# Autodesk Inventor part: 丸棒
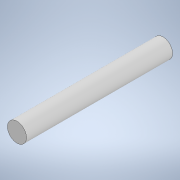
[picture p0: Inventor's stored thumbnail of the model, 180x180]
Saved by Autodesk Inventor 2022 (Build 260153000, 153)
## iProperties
Created: 2024-12
Part Number: 丸棒
Material: 一般
Document SubType Name: Modeling
Designer: jsat7
Density: 1 g/cm^3
Appearance: 既定
Author: jsat7
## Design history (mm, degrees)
sketch "スケッチ1"
  geometry: C1 r 1.5 at (0, 0); 1 further point
  constraints: 1 centre point, 1 coincident
  dimensions: "d0" = 3 diameter of C1
extrude "押し出し1" new body sketch "スケッチ1" distance "d1" = 23; taper "d2" = 0 deg
node "ソリッド1"
